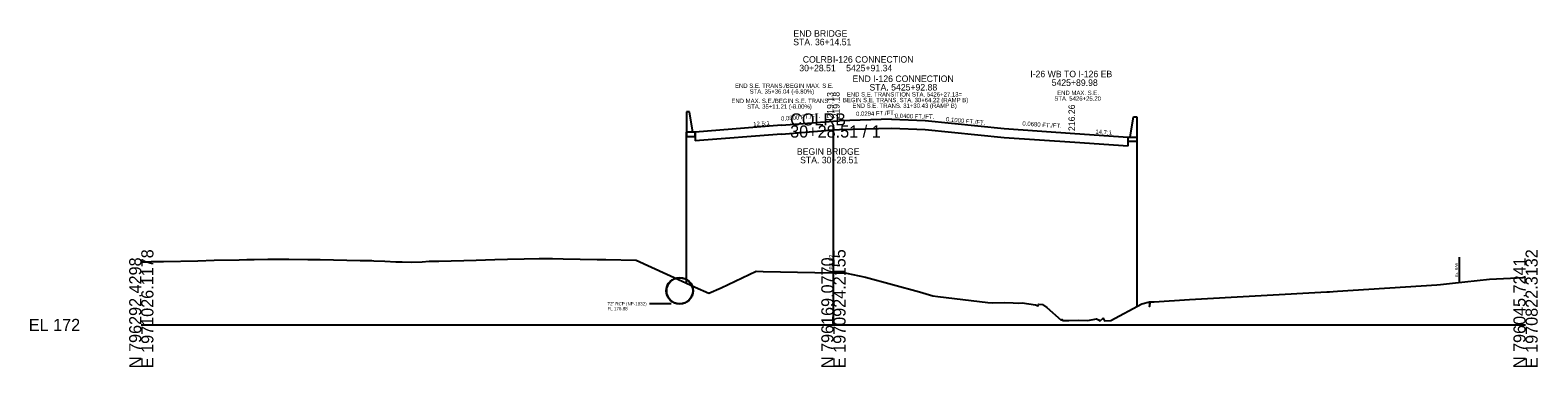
# Model space of a CAD drawing. Extents: x -26 to 1971766, y -10 to 796432.
# Drawn here: x -25.7 to 322.8, y -9.7 to 68.1 of the extents above; entities that cross this region are included whole.
import ezdxf

# ---------------------------------------------------------------- set-up
doc = ezdxf.new("R2010")
doc.units = 0
for name, color, linetype in [('BR_BORDER LINES', 7, 'Continuous'), ('BR_CONCRETE', 7, 'Continuous'), ('BR_STRUCTURAL STEEL', 7, 'Continuous'), ('BR_TABLE LINES', 7, 'Continuous'), ('Default', 7, 'Continuous'), ('North Arrow', 7, 'Continuous'), ('RD_EX_Road', 7, 'Continuous'), ('RD_HC_CL_Rel', 7, 'Continuous'), ('RD_PD_ALT1_TrvlWay', 7, 'Continuous'), ('RD_PD_ALT2_TnTmp', 7, 'Continuous'), ('RD_PD_FOC', 7, 'Continuous'), ('RD_PD_GR', 7, 'Continuous'), ('RD_PD_MedBWall', 7, 'Continuous'), ('RD_PD_WallFill', 7, 'Continuous'), ('RD_SHT_IplotShp', 7, 'Continuous')]:
    doc.layers.add(name, color=color, linetype=linetype)

msp = doc.modelspace()

# ---------------------------------------------------------------- linework, layer by layer
at = {"layer": 'BR_BORDER LINES'}
msp.add_lwpolyline([(0, 14.59), (0.9, 14.6), (1.34, 14.61), (2.27, 14.65), (5.13, 14.68), (13.1, 14.85), (16.86, 14.93), (22.65, 15.07), (24.4, 15.12), (26.12, 15.16), (29.27, 15.23), (31.94, 15.22), (34.08, 15.21), (38.49, 15.12), (41.33, 15.09), (50.63, 14.91), (53.3, 14.86), (53.78, 14.85), (56.29, 14.7), (58.86, 14.62), (59.58, 14.6), (60.28, 14.59), (62.38, 14.54), (64.94, 14.6), (66.57, 14.71), (68, 14.74), (68.76, 14.76), (77.44, 15), (81.73, 15.14), (84.64, 15.19), (88.48, 15.26), (92, 15.34), (93.92, 15.37), (95.04, 15.35), (97.5, 15.28), (105.37, 15.13), (106.54, 15.11), (107.36, 15.09), (114.37, 14.93), (125, 10.11), (128.04, 8.72), (131.2, 7.32), (134.01, 8.58), (142.13, 12.43), (143.77, 12.35), (155.73, 12.1), (160, 12.02), (163, 11.96), (167.44, 11.01), (179.92, 7.61), (182.99, 6.75), (184.13, 6.54), (195.68, 5.16), (196.77, 5.12), (199.54, 5.16), (201.54, 5.09), (202.67, 5.06), (203.66, 5.14), (206.74, 4.64), (207.3, 4.39), (207.38, 4.8), (208.32, 4.7), (209.33, 4.01), (212.64, 1.11), (212.86, 1.25), (213.06, 1.05), (214.45, 1), (216.55, 1.11), (218.79, 1.04), (220.85, 1.37), (221.25, 1.18), (221.7, 0.93), (222.32, 1.54), (222.66, 0.97), (224.11, 1), (231.26, 4.85), (233.06, 5.36), (233.1, 4.27), (233.3, 5.37), (234.12, 5.35), (242.32, 5.84), (274.03, 7.64), (274.71, 7.67), (275.54, 7.71), (276.53, 7.8), (299.46, 9.28), (300.34, 9.36), (303.12, 9.62), (311.67, 10.56), (316.48, 10.81), (319.37, 10.98), (320, 11.16)], dxfattribs=at)
at = {"layer": 'BR_STRUCTURAL STEEL'}
for p, q in [((128, 44.57), (125.95, 44.57)), ((125.95, 44.57), (125.95, 9.67)), ((128, 44.57), (125.95, 44.57)), ((228.12, 43.43), (230.16, 43.43)), ((228.12, 43.43), (230.17, 43.43)), ((230.16, 43.43), (230.16, 4.26))]:
    msp.add_line(p, q, dxfattribs=at)
at = {"layer": 'BR_TABLE LINES'}
msp.add_line((304.64, 15.66), (304.64, 9.66), dxfattribs=at)
at = {"layer": 'Default'}
for p, q in [((160, 0), (160, 46.11)), ((0, 0), (160, 0)), ((160, 0), (320, 0))]:
    msp.add_line(p, q, dxfattribs=at)
at = {"layer": 'North Arrow'}
for p, q in [((148, 46.17), (160, 47.13)), ((173.46, 47.53), (161.42, 47.18)), ((199.48, 45.4), (215.84, 44.26))]:
    msp.add_line(p, q, dxfattribs=at)
at = {"layer": 'RD_EX_Road'}
for p, q in [((161.42, 45.14), (173.46, 45.49)), ((173.46, 45.49), (181.24, 45.18)), ((128, 44.57), (128, 42.53)), ((148, 44.13), (128, 42.53)), ((148, 44.13), (160, 45.09)), ((160, 45.09), (161.42, 45.14)), ((181.24, 45.18), (199.48, 43.36)), ((199.48, 43.36), (215.84, 42.22)), ((215.84, 42.22), (228.12, 41.39)), ((228.12, 41.39), (228.12, 43.43))]:
    msp.add_line(p, q, dxfattribs=at)
at = {"layer": 'RD_PD_FOC'}
msp.add_line((122.46, 4.88), (117.46, 4.88), dxfattribs=at)
for radius in [3.1, 3]:
    msp.add_circle((124.46, 7.88), radius, dxfattribs=at)
at = {"layer": 'RD_PD_GR'}
for p, q in [((126.75, 49.24), (126, 49.24)), ((126, 49.24), (126, 43.57)), ((127.5, 44.57), (126.75, 49.24)), ((228.62, 43.43), (229.37, 48.09)), ((229.37, 48.09), (230.12, 48.09)), ((230.12, 48.09), (230.12, 42.43)), ((126, 43.57), (128, 43.57)), ((128, 44.57), (127.5, 44.57)), ((128, 43.57), (128, 44.57)), ((228.12, 42.43), (228.12, 43.43)), ((228.12, 43.43), (228.62, 43.43)), ((230.12, 42.43), (228.12, 42.43))]:
    msp.add_line(p, q, dxfattribs=at)
at = {"layer": 'RD_PD_MedBWall'}
for p, q in [((148, 46.17), (128, 44.57)), ((160, 47.13), (161.42, 47.18)), ((173.46, 47.53), (181.24, 47.22)), ((181.24, 47.22), (199.48, 45.4)), ((215.84, 44.26), (228.12, 43.43))]:
    msp.add_line(p, q, dxfattribs=at)

# ---------------------------------------------------------------- texts
at = {"layer": 'BR_CONCRETE'}
for s, rotation, p in [('0.0800 FT./FT.', 4.5739, (147.92, 47.17)), ('0.0294 FT./FT.', 1.6824, (165.24, 48.29)), ('0.0400 FT./FT.', 358.6524, (174.17, 47.86)), ('0.1000 FT./FT.', 354.3242, (185.99, 47.08)), ('0.0680 FT./FT.', 356.1097, (203.65, 46.09))]:
    msp.add_text(s, height=1, rotation=rotation, dxfattribs=at).set_placement(p)
at = {"layer": 'BR_TABLE LINES'}
msp.add_text('Ex. R/W ', height=0.65, rotation=90, dxfattribs=at).set_placement((304.39, 11.05))
at = {"layer": 'Default'}
for s, p in [('COLRB', (150, 46.11)), ('30+28.51 / 1', (150, 43.31)), ('EL 172', (-26, -1.4))]:
    msp.add_text(s, height=2.8, dxfattribs=at).set_placement(p)
for s, p in [('N 796292.4298', (0, -10)), ('E 1971026.1178', (2.8, -10)), ('N 796169.0770', (160, -10)), ('E 1970924.2155', (162.8, -10)), ('N 796045.7241', (320, -10)), ('E 1970822.3132', (322.8, -10))]:
    msp.add_text(s, height=2.8, rotation=90, dxfattribs=at).set_placement(p)
at = {"layer": 'RD_HC_CL_Rel'}
for s, p in [(' 219.13', (160, 47.13)), (' 219.18', (161.42, 47.18)), (' 216.26', (215.84, 44.26))]:
    msp.add_text(s, height=1.5, rotation=90, dxfattribs=at).set_placement(p)
at = {"layer": 'RD_PD_ALT1_TrvlWay'}
for s, rotation, p in [('12.5:1', 4.5739, (141.5, 45.9)), ('14.7:1', 356.1136, (220.52, 44.19))]:
    msp.add_text(s, height=1, rotation=rotation, dxfattribs=at).set_placement(p)
at = {"layer": 'RD_PD_ALT2_TnTmp'}
for s, height, p in [('END BRIDGE', 1.5, (150.74, 66.62)), ('STA. 36+14.51', 1.5, (150.71, 64.65)), ('END S.E. TRANS./BEGIN MAX. S.E. ', 1, (137.25, 54.79)), ('END I-126 CONNECTION', 1.5, (164.4, 56.16)), ('END MAX. S.E./BEGIN S.E. TRANS.', 1, (136.41, 51.29)), ('STA. 35+36.04 (-6.80%)', 1, (140.63, 53.47)), ('BEGIN S.E. TRANS. STA. 30+64.22 (RAMP B)', 1, (162.19, 51.49)), ('END S.E. TRANSITION STA. 5426+27.13=', 1, (163.1, 52.8)), ('STA. 5425+92.88', 1.5, (168.33, 54.19)), (' STA. 5426+25.20', 1, (210.69, 51.84)), ('END MAX. S.E.', 1, (211.72, 53.15)), (' STA. 35+11.21 (-8.00%)', 1, (139.68, 49.98)), ('END S.E. TRANS. 31+30.43 (RAMP B)', 1, (164.39, 50.18)), ('BEGIN BRIDGE', 1.5, (151.55, 39.33)), ('STA. 30+28.51', 1.5, (152.3, 37.37))]:
    msp.add_text(s, height=height, dxfattribs=at).set_placement(p)
at = {"layer": 'RD_PD_FOC'}
for s, p in [('72" RCP (NP-1832)', (107.77, 4.51)), ('FL 176.88', (107.77, 3.38))]:
    msp.add_text(s, height=0.75, dxfattribs=at).set_placement(p)
at = {"layer": 'RD_PD_WallFill'}
for s, p in [('30+28.51', (152.11, 58.63)), ('COLRB', (152.91, 60.63)), ('I-126 CONNECTION', (159.89, 60.63)), ('5425+91.34', (162.94, 58.63)), ('I-26 WB TO I-126 EB', (205.5, 57.26)), ('5425+89.98', (210.45, 55.26))]:
    msp.add_text(s, height=1.5, dxfattribs=at).set_placement(p)
at = {"layer": 'RD_SHT_IplotShp'}
msp.add_text('184.02', height=1, rotation=90, dxfattribs=at).set_placement((160, 12.02))

doc.saveas('drawing.dxf')
